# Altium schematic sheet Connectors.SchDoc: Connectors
size A4; Date: Not used; ApprovedBy: Not used; CheckedBy: Not used; Author: Not used; CompanyName: STMicroelectronics; DrawnBy: Not used; Engineer: Not used; Organization: Not used; Address1: Not used; Address2: Not used; Address3: Not used; Address4: Not used; DocumentNumber: Not used; Revision: Not used; SheetNumber: 6; SheetTotal: 6
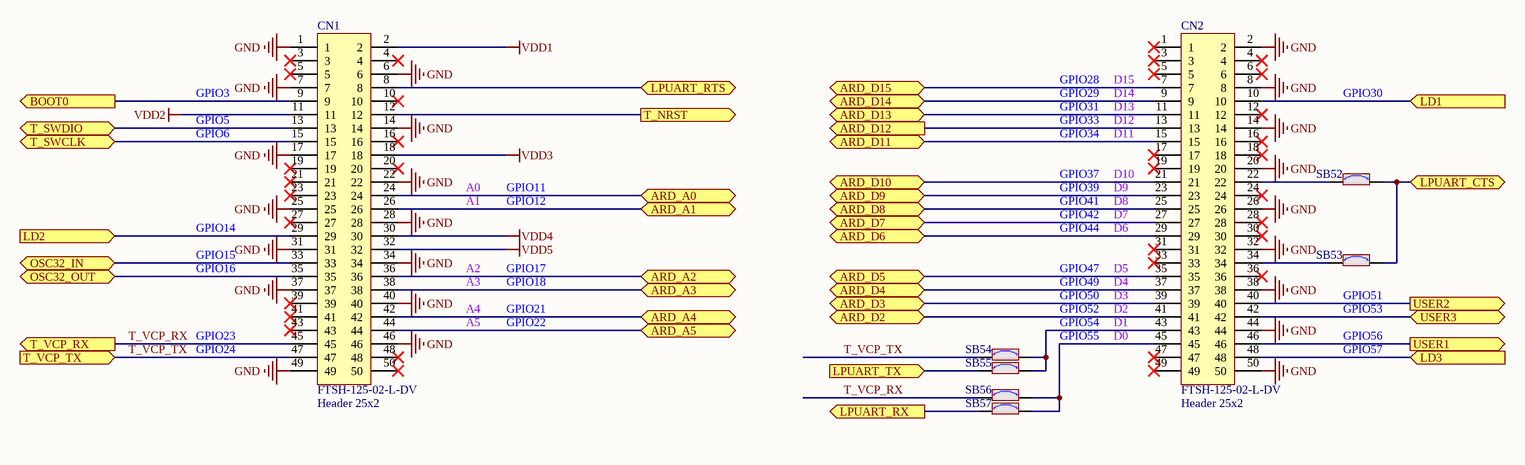
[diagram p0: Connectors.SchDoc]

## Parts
CN1  FTSH-125-02-L-DV  value Header 25x2  [CON_SAMTEC_FTSH-125-02-L-DV]
CN2  FTSH-125-02-L-DV  value Header 25x2  [CON_SAMTEC_FTSH-125-02-L-DV]
SB52  SB_ON  [SOLDER-BRIDGE_R0402-0R]  (value not drawn)
SB53  SB_ON  [SOLDER-BRIDGE_R0402-0R]  (value not drawn)
SB54  SB_ON  [SOLDER-BRIDGE_R0402-0R]  (value not drawn)
SB55  SB_ON  [SOLDER-BRIDGE_R0402-0R]  (value not drawn)
SB56  SB_ON  [SOLDER-BRIDGE_R0402-0R]  (value not drawn)
SB57  SB_ON  [SOLDER-BRIDGE_R0402-0R]  (value not drawn)

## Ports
ARD_A0 (bidir), ARD_A1 (bidir), ARD_A2 (bidir), ARD_A3 (bidir), ARD_A4 (bidir), ARD_A5 (bidir), ARD_D2 (bidir), ARD_D3 (bidir), ARD_D4 (bidir), ARD_D5 (bidir), ARD_D6 (bidir), ARD_D7 (bidir), ARD_D8 (bidir), ARD_D9 (bidir), ARD_D10 (bidir), ARD_D11 (bidir), ARD_D12 (out), ARD_D13 (bidir), ARD_D14 (bidir), ARD_D15 (bidir), BOOT0 (out), LD1 (in), LD2 (in), LD3 (in), LPUART_CTS (bidir), LPUART_RTS (bidir), LPUART_RX (out), LPUART_TX (in), OSC32_IN (bidir), OSC32_OUT (bidir), T_NRST (out), T_SWCLK (bidir), T_SWDIO (bidir), T_VCP_RX (out), T_VCP_TX (in), USER1 (out), USER2 (out), USER3 (bidir)

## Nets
GND: CN1.1 CN1.6 CN1.7 CN1.14 CN1.17 CN1.22 CN1.25 CN1.28 CN1.31 CN1.34 CN1.37 CN1.40 CN1.46 CN1.49 CN2.2 CN2.8 CN2.14 CN2.20 CN2.26 CN2.32 CN2.38 CN2.44 CN2.50
VDD1: CN1.2
VDD2: CN1.11
VDD3: CN1.18
VDD4: CN1.30
VDD5: CN1.32
ARD_A0: CN1.24 ; port ARD_A0
ARD_A1: CN1.26 ; port ARD_A1
ARD_A2: CN1.36 ; port ARD_A2
ARD_A3: CN1.38 ; port ARD_A3
ARD_A4: CN1.42 ; port ARD_A4
ARD_A5: CN1.44 ; port ARD_A5
ARD_D2: CN2.41 ; port ARD_D2
ARD_D3: CN2.39 ; port ARD_D3
ARD_D4: CN2.37 ; port ARD_D4
ARD_D5: CN2.35 ; port ARD_D5
ARD_D6: CN2.29 ; port ARD_D6
ARD_D7: CN2.27 ; port ARD_D7
ARD_D8: CN2.25 ; port ARD_D8
ARD_D9: CN2.23 ; port ARD_D9
ARD_D10: CN2.21 ; port ARD_D10
ARD_D11: CN2.15 ; port ARD_D11
ARD_D12: CN2.13 ; port ARD_D12
ARD_D13: CN2.11 ; port ARD_D13
ARD_D14: CN2.9 ; port ARD_D14
ARD_D15: CN2.7 ; port ARD_D15
BOOT0: CN1.9 ; port BOOT0
LD1: CN2.10 ; port LD1
LD2: CN1.29 ; port LD2
LD3: CN2.48 ; port LD3
LPUART_CTS: SB52.2 SB53.2 ; port LPUART_CTS
LPUART_RTS: CN1.8 ; port LPUART_RTS
LPUART_RX: SB57.1 ; port LPUART_RX
LPUART_TX: SB55.1 ; port LPUART_TX
OSC32_IN: CN1.33 ; port OSC32_IN
OSC32_OUT: CN1.35 ; port OSC32_OUT
T_NRST: CN1.12 ; port T_NRST
T_SWCLK: CN1.15 ; port T_SWCLK
T_SWDIO: CN1.13 ; port T_SWDIO
T_VCP_RX: CN1.45 SB56.1 ; port T_VCP_RX
T_VCP_TX: CN1.47 SB54.1 ; port T_VCP_TX
USER1: CN2.46 ; port USER1
USER2: CN2.40 ; port USER2
USER3: CN2.42 ; port USER3
NetCN2_22: CN2.22 SB52.1
NetCN2_34: CN2.34 SB53.1
NetCN2_43: CN2.43 SB54.2 SB55.2
NetCN2_45: CN2.45 SB56.2 SB57.2

Not connected (* = marked no-connect by the designer): CN1 3* 4* 5* 10* 16* 19* 20* 21* 23* 27* 39* 41* 43* 48* 50*; CN2 1* 3* 4* 5* 6* 12* 16* 17* 18* 19* 24* 28* 30* 31* 33* 36* 47* 49*

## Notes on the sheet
- GPIO3
- GPIO5
- GPIO28
- GPIO29
- GPIO31
- GPIO33
- (near CN2) D12
- (near CN2) D13
- (near CN2) D14
- (near CN2) D15
- GPIO30
- GPIO6
- A0
- GPIO11
- GPIO34
- GPIO37
- GPIO39
- D9
- (near CN2) D10
- (near CN2) D11
- GPIO14
- GPIO15
- A1
- GPIO12
- GPIO41
- GPIO42
- GPIO44
- D8
- D7
- D6
- GPIO16
- A2
- A3
- A4
- A5
- GPIO17
- GPIO18
- GPIO21
- GPIO22
- GPIO54
- GPIO52
- GPIO47
- GPIO49
- GPIO50
- D1
- D2
- D5
- D4
- D3
- (near SB53) GPIO51
- (near SB53) GPIO53
- GPIO23
- GPIO24
- GPIO55
- D0
- GPIO56
- GPIO57

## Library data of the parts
CN1 CN2 = MCD-02746: Header, 25x2, 12.7mm, VR, SMD, T=4.83mm; Part_Type: Connector; Part_Preference: Recommended; Manufacturer: SAMTEC; Component_Country_Of_Origin: China, Costa Rica, Malaysia, USA, Vietnam; ShowFields: YES; ID: 4858
SB52-SB57 = MCD-01618: Solder Bridge 0402 ON; Part_Type: Resistor; Part_Preference: Recommended; Manufacturer: YAGEO; Manufacturer_Part_Number: RC0402JR-070RL; Value: 0R; Order_Code_RS: 618-5804; Component_Country_Of_Origin: China; ShowFields: YES; ID: 3718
